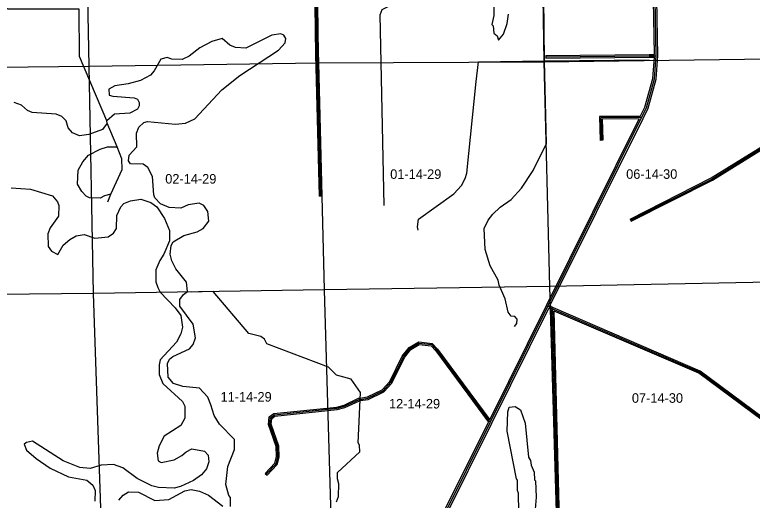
# Model space of a CAD drawing. Extents: x 457167 to 656239, y 1787309 to 1969297.
# Drawn here: x 542162 to 559531, y 1802811 to 1814251 of the extents above; entities that cross this region are included whole.
import ezdxf

# ---------------------------------------------------------------- set-up
doc = ezdxf.new("R2010")
doc.units = 0
for name, color, linetype in [('Level 1', 7, 'Continuous'), ('Level 2', 7, 'Continuous'), ('Level 22', 7, 'Continuous'), ('Level 23', 7, 'Continuous'), ('Level 31', 7, 'Continuous'), ('Level 32', 7, 'Continuous'), ('Level 34', 7, 'Continuous'), ('Level 5', 7, 'Continuous'), ('Level 7', 7, 'Continuous')]:
    doc.layers.add(name, color=color, linetype=linetype)

msp = doc.modelspace()

# ---------------------------------------------------------------- linework, layer by layer
at = {"layer": 'Level 1'}
for p, q in [((543913.495, 1813038.625), (543806.772, 1818560.041)), ((549159.663, 1818551.891), (549316.915, 1813116.23)), ((554522.895, 1818595.745), (554626.091, 1813144.464)), ((554626.091, 1813144.464), (559933.526, 1813210.771)), ((538646.1, 1812984.036), (543913.495, 1813038.625)), ((543913.495, 1813038.625), (549316.915, 1813116.23)), ((544019.338, 1807683.474), (543913.495, 1813038.625)), ((549316.915, 1813116.23), (554626.091, 1813144.464)), ((549316.915, 1813116.23), (549446.786, 1807768.911)), ((554626.091, 1813144.464), (554754.302, 1807847.236)), ((560083.97, 1807951.436), (554754.302, 1807847.236)), ((554754.302, 1807847.236), (549446.786, 1807768.911)), ((554754.302, 1807847.236), (554912.4, 1802537.764)), ((544019.338, 1807683.474), (538702.035, 1807635.269)), ((549446.786, 1807768.911), (544019.338, 1807683.474)), ((544199.322, 1802359.816), (544019.338, 1807683.474)), ((549446.786, 1807768.911), (549606.588, 1802415.358))]:
    msp.add_line(p, q, dxfattribs=at)
at = {"layer": 'Level 22'}
for p, q in [((557268.834, 1813284.999), (557241.795, 1814628.309)), ((554718.957, 1807381.432), (556924.929, 1811827.401)), ((553360.949, 1804642.301), (554718.957, 1807381.432)), ((550520.034, 1798947.821), (553360.949, 1804642.301))]:
    msp.add_line(p, q, dxfattribs=at)
msp.add_lwpolyline([(556924.929, 1811827.401), (557040.277, 1812060.181), (557225.653, 1812743.309), (557268.834, 1813284.999)], dxfattribs=at)
at = {"layer": 'Level 23'}
for p, q in [((557228.23, 1813314.579), (557202.395, 1814598.118)), ((557308.868, 1813283.809), (557281.788, 1814629.114)), ((554683.125, 1807399.21), (556865.177, 1811796.969)), ((554767.031, 1807388.324), (556960.761, 1811809.622)), ((553349.241, 1804708.737), (554683.12, 1807399.199)), ((553396.787, 1804624.533), (554740.32, 1807334.464)), ((550502.28, 1799001.834), (553319.245, 1804648.311)), ((550555.828, 1798929.964), (553396.743, 1804624.444))]:
    msp.add_line(p, q, dxfattribs=at)
for points in [[(556895.047, 1811857.186), (557002.698, 1812074.435), (557186.075, 1812750.196), (557226.28, 1813254.555)], [(556960.77, 1811809.641), (557077.855, 1812045.928), (557265.231, 1812736.422), (557308.868, 1813283.809)]]:
    msp.add_lwpolyline(points, dxfattribs=at)
at = {"layer": 'Level 31'}
for p, q in [((554667.655, 1813258.509), (557101.201, 1813283.261)), ((557101.201, 1813283.261), (557268.834, 1813284.999)), ((554835.432, 1807314.209), (554718.957, 1807381.432))]:
    msp.add_line(p, q, dxfattribs=at)
for points in [[(549365.557, 1809979.888), (549282.662, 1813314.591), (549262.15, 1815056.791), (549179.714, 1818541.679)], [(556924.929, 1811827.401), (555965.95, 1811820.502), (555978.873, 1811291.39)], [(556666.727, 1809410.332), (558578.061, 1810380.549), (560056.031, 1811293.429)], [(560237.928, 1804424.068), (560021.472, 1804541.346), (558291.11, 1805829.426), (554835.432, 1807314.209)], [(555060.472, 1797876.787), (555028.798, 1798543.761), (554956.38, 1802654.014), (554835.432, 1807314.209)], [(550295.708, 1805187.916), (550478.118, 1805216.854), (550837.206, 1805390.746), (551021.051, 1805590.589), (551314.388, 1806189.75), (551473.364, 1806389.664), (551682.17, 1806514.168), (551982.013, 1806479.879), (552098.642, 1806354.467), (553360.949, 1804642.301)], [(548081, 1803422.288), (548315.058, 1803671.788), (548356.978, 1803838.572), (548349.387, 1804080.406), (548167.271, 1804597.645), (548184.623, 1804756.136), (548276.298, 1804822.415), (549752.27, 1804977.097), (549927.406, 1805026.416), (550269.879, 1805183.988), (550295.708, 1805187.916)]]:
    msp.add_lwpolyline(points, dxfattribs=at)
at = {"layer": 'Level 32'}
for p, q in [((554667.35, 1813288.507), (557100.897, 1813313.259)), ((554667.35, 1813288.507), (554667.96, 1813228.509)), ((554667.96, 1813228.509), (557101.506, 1813253.261)), ((557100.891, 1813313.259), (557228.23, 1813314.579)), ((557101.512, 1813253.261), (557226.28, 1813254.555)), ((556008.865, 1811292.123), (555948.882, 1811290.657)), ((549335.566, 1809979.143), (549395.549, 1809980.633)), ((556653.148, 1809437.083), (556680.307, 1809383.581)), ((554805.879, 1807296.626), (554740.32, 1807334.464)), ((554848.9, 1807341.075), (554767.032, 1807388.324)), ((548059.12, 1803442.814), (548102.88, 1803401.762))]:
    msp.add_line(p, q, dxfattribs=at)
for points in [[(549395.549, 1809980.633), (549312.659, 1813315.141), (549292.147, 1815057.323), (549209.705, 1818542.389)], [(549335.566, 1809979.143), (549252.666, 1813314.042), (549232.155, 1815056.261), (549149.722, 1818540.969)], [(556895.047, 1811857.187), (555935.213, 1811850.282), (555948.882, 1811290.657)], [(556865.176, 1811796.969), (555996.686, 1811790.722), (556008.865, 1811292.123)], [(556653.148, 1809437.083), (558563.363, 1810406.732), (560037.328, 1811317.137)], [(556680.307, 1809383.581), (558592.76, 1810354.366), (560027.587, 1811240.598)], [(555030.505, 1797875.364), (554998.81, 1798542.785), (554926.386, 1802653.361), (554805.88, 1807296.626)], [(560206.863, 1804475.021), (560037.658, 1804566.698), (558306.194, 1805855.597), (554848.9, 1807341.075)], [(560211.777, 1804404.115), (560005.286, 1804515.995), (558276.025, 1805803.254), (554866.639, 1807268.148)], [(555090.438, 1797878.21), (555058.785, 1798544.737), (554986.375, 1802654.668), (554866.639, 1807268.147)], [(550291.199, 1805217.575), (550469.036, 1805245.788), (550818.992, 1805415.259), (550996.023, 1805607.694), (551288.877, 1806205.87), (551453.294, 1806412.625), (551675.51, 1806545.126), (551996.434, 1806508.426), (552121.775, 1806373.646), (553349.241, 1804708.737)], [(550300.409, 1805158.286), (550487.2, 1805187.919), (550855.42, 1805366.234), (551046.08, 1805573.484), (551339.898, 1806173.63), (551493.435, 1806366.703), (551688.83, 1806483.211), (551967.592, 1806451.331), (552075.51, 1806335.289), (553319.245, 1804648.311)], [(548059.12, 1803442.814), (548287.859, 1803686.642), (548326.861, 1803841.82), (548319.547, 1804074.822), (548136.705, 1804594.121), (548156.251, 1804772.643), (548265.209, 1804851.418), (549746.599, 1805006.667), (549917.007, 1805054.656), (550261.185, 1805213.012), (550291.199, 1805217.575)], [(548102.88, 1803401.762), (548342.258, 1803656.934), (548387.095, 1803835.324), (548379.228, 1804085.988), (548197.836, 1804601.167), (548212.995, 1804739.628), (548287.388, 1804793.412), (549757.94, 1804947.526), (549937.806, 1804998.178), (550278.572, 1805154.965), (550300.218, 1805158.256)]]:
    msp.add_lwpolyline(points, dxfattribs=at)
at = {"layer": 'Level 5'}
for p, q in [((554640.334, 1813164.453), (554620.229, 1814706.756)), ((554640.334, 1813164.453), (557099.632, 1813189.983)), ((544340.238, 1811696.744), (544332.097, 1811755.095)), ((544571.887, 1811137.458), (544340.238, 1811696.744)), ((544351.016, 1809846.016), (544426.605, 1810020.85))]:
    msp.add_line(p, q, dxfattribs=at)
for points in [[(550861.428, 1809758.605), (550767.393, 1814252.191), (550817.803, 1814377.064), (551118.396, 1814526.17), (551177.046, 1814626.012), (551168.975, 1814709.403), (551085.903, 1814793.034), (550994.341, 1814843.343), (550994.5, 1814885.024), (551220.86, 1815284.453), (551479.972, 1815508.709), (552540.932, 1816213.893), (553093.684, 1817012.441), (553546.234, 1817761.269), (553596.514, 1817844.471)], [(544332.097, 1811755.095), (543686.672, 1813266.06), (543681.901, 1814383.116), (542006.275, 1814380.146), (541914.714, 1814422.116), (541781.75, 1814555.896), (541481.815, 1814606.893), (541415.254, 1814640.432), (541457.363, 1814782.015), (541571.029, 1816440.581), (541572.405, 1816865.728)], [(551659.855, 1809172.516), (551643.445, 1809255.906), (551669.003, 1809430.9), (552504.56, 1810028.469), (552680.251, 1810227.984), (552772.471, 1810394.418), (552806.24, 1810519.33), (553029.854, 1812677.736), (553081.35, 1813144.413), (554640.334, 1813164.453)], [(553928.462, 1806906.119), (553987.012, 1806972.651), (553995.701, 1807080.983), (553937.52, 1807139.503), (553854.189, 1807148.132), (553779.456, 1807240.062), (553713.773, 1807557.036), (553573.107, 1807882.61), (553548.455, 1807999.411), (553357.8, 1808333.454), (553242.305, 1808717.288), (553218.9, 1809217.556), (553311.189, 1809409), (553420.02, 1809550.353), (553595.6, 1809716.528), (553854.623, 1809899.104), (554097.224, 1810165.081), (554373.665, 1810581.051), (554684.133, 1811213.624), (554640.334, 1813164.453)], [(544426.605, 1810020.85), (544695.224, 1810603.541), (544687.681, 1810853.666), (544571.887, 1811137.458)], [(549738.757, 1802776.326), (549789.196, 1802901.208), (549798.484, 1803201.282), (549765.502, 1803318.084), (549765.99, 1803468.136), (550292.714, 1803949.98), (550284.873, 1804108.392), (550251.721, 1804166.852), (550305.501, 1805350.441), (550081.435, 1805667.933), (549739.949, 1805760.711), (549548.794, 1805944.731), (548100.046, 1806499.541), (548042.024, 1806608.102), (547958.862, 1806666.722), (547675.657, 1806742.63), (546836.825, 1807728.995), (546328.287, 1807713.958)]]:
    msp.add_lwpolyline(points, dxfattribs=at)
at = {"layer": 'Level 7'}
for points in [[(553445.668, 1814977.246), (553443.305, 1814235.314), (553400.936, 1814018.701), (553425.847, 1813993.631), (553441.969, 1813818.508), (553525.131, 1813751.548), (553558.153, 1813651.416), (553675.323, 1813792.741), (553759.462, 1814042.565), (553793.53, 1814267.549)], [(544887.385, 1810736.306), (544837.594, 1810811.496), (544854.693, 1810944.809), (545038.714, 1811135.954), (545031.43, 1811461.099), (545081.87, 1811602.651), (545198.941, 1811710.665), (545290.702, 1811735.386), (545949.103, 1811674.933), (546182.586, 1811699.196), (546399.659, 1811798.541), (547035.372, 1812480.089), (547461.635, 1812820.539), (548372.194, 1813417.84), (548531.135, 1813592.414), (548548.144, 1813692.386), (548498.353, 1813767.576), (548431.761, 1813801.116), (548214.918, 1813768.453), (547605.381, 1813461.971), (547363.698, 1813479.398), (547230.515, 1813538.177), (547047.57, 1813688.817), (546805.628, 1813622.913), (546521.705, 1813473.747), (546270.993, 1813274.491), (546104, 1813199.988), (545862.247, 1813200.776), (545754.005, 1813242.775), (545603.823, 1813201.592), (545444.583, 1812926.976), (545360.893, 1812827.203), (545127.09, 1812702.919), (544835.056, 1812620.504), (544518.142, 1812579.8), (544376.13, 1812496.896), (544384.042, 1812355.145), (544475.644, 1812329.875), (544975.722, 1812294.931), (545050.654, 1812261.321), (545092.075, 1812186.161), (545091.805, 1812102.799), (545049.895, 1812027.907), (544874.514, 1811928.454), (544507.649, 1811904.589), (544332.097, 1811755.095)], [(544340.238, 1811696.744), (544231.408, 1811547.011), (543905.894, 1811431.355), (543689.06, 1811398.691), (543522.557, 1811465.911), (543422.885, 1811582.941), (543373.392, 1811749.833), (543273.68, 1811850.193), (543140.497, 1811908.972), (542573.728, 1811944.116), (542465.515, 1811994.466), (542324.192, 1812119.966), (542149.359, 1812187.215)], [(544426.605, 1810020.85), (544276.454, 1809987.967), (544176.222, 1809929.936), (543926.159, 1809939.092), (543842.897, 1809972.701), (543743.254, 1810089.702), (543643.741, 1810256.754), (543653.128, 1810590.169), (543762.118, 1810781.583), (543896.028, 1810939.547), (544171.551, 1811080.382), (544346.803, 1811138.176), (544571.887, 1811137.458)], [(547245.85, 1802667.523), (547246.538, 1802875.936), (547204.986, 1802926.116), (547130.813, 1803184.77), (547182.17, 1803609.756), (547333.498, 1804009.405), (547334.246, 1804242.828), (546985.267, 1804602.399), (546860.883, 1804811.201), (546778.3, 1805061.583), (546712.167, 1805236.836), (546512.822, 1805454.236), (546121.115, 1805488.822), (545904.601, 1805564.531), (545771.708, 1805715.011), (545756.045, 1806031.826), (545806.365, 1806131.728), (545881.615, 1806198.16), (546274.009, 1806380.317), (546366.04, 1806480.06), (546416.549, 1806638.283), (546367.575, 1806963.557), (546052.106, 1807381.39), (546052.625, 1807539.782), (546136.355, 1807656.225), (546228.275, 1807730.957), (546203.993, 1807947.771), (545954.886, 1808265.332), (545863.773, 1808449.024), (545822.61, 1808607.546), (545848.279, 1808815.879), (545890.219, 1808899.111), (546140.801, 1809048.386), (546457.875, 1809139.071), (546599.817, 1809213.634), (546733.757, 1809388.278), (546709.465, 1809613.421), (546618.232, 1809755.432), (546501.68, 1809814.182), (546243.126, 1809773.318), (546076.144, 1809690.475), (545801.11, 1809708.031), (545592.965, 1809792.051), (545460.042, 1809934.191), (545435.261, 1810009.312), (545403.286, 1810442.898), (545295.603, 1810651.63), (545187.46, 1810727.02), (544887.385, 1810736.306)], [(542076.228, 1810170.053), (542534.655, 1810143.578), (543050.985, 1809983.552), (543167.228, 1809841.441), (543200.319, 1809757.981), (543191.191, 1809507.926), (542998.581, 1809233.451), (542939.761, 1809091.897), (542947.155, 1808791.793), (543030.187, 1808683.162), (543179.95, 1808599.303), (543305.71, 1808823.988), (543456.19, 1808956.881), (543606.502, 1809039.755), (543798.365, 1809072.507), (544048.16, 1808988.33), (544365.074, 1809020.694), (544490.375, 1809103.636), (544557.395, 1809211.809), (544566.712, 1809520.214), (544659.102, 1809728.328), (544734.352, 1809803.131), (544884.604, 1809869.333), (545134.828, 1809901.886), (545367.982, 1809826.108), (545509.405, 1809725.618), (545691.92, 1809449.926), (545807.705, 1809166.134), (545806.957, 1808924.39), (545672.558, 1808608.034), (545580.369, 1808458.271), (545487.989, 1808241.826), (545487.072, 1807958.391), (545528.324, 1807824.88), (545586.355, 1807716.309), (545943.635, 1807348.368), (546076.429, 1807164.546), (546108.891, 1806889.353), (546075.053, 1806731.061), (545974.393, 1806539.656), (545589.581, 1806115.745), (545564.212, 1805999.103), (545563.494, 1805774.02), (545646.167, 1805565.357), (546111.659, 1805138.726), (546169.66, 1805030.166), (546168.773, 1804746.731), (546076.514, 1804571.957), (545683.89, 1804323.119), (545566.47, 1804090.054), (545515.891, 1803923.501), (545540.313, 1803740.028), (545606.875, 1803698.118), (545915.539, 1803763.833), (546099.27, 1803863.277), (546199.561, 1803954.68), (546333.173, 1804020.952), (546633.118, 1803969.956), (546716.15, 1803869.655), (546732.372, 1803719.562)], [(554038.12, 1802087.387), (554024.3, 1802979.401), (553999.49, 1803037.821), (554000.267, 1803287.906), (553975.356, 1803313.016), (553762.183, 1804439.1), (553771.989, 1804897.567), (553805.698, 1805005.839), (553947.45, 1805022.051), (554072.233, 1804938.301), (554179.617, 1804629.498), (554260.426, 1803828.946), (554310.188, 1803745.426), (554326.499, 1803637.025), (554392.661, 1803470.063), (554400.444, 1803294.971), (554425.354, 1803269.901), (554440.818, 1802886.365), (554371.415, 1802036.291)], [(546732.372, 1803719.562), (546681.793, 1803553.01), (546556.322, 1803411.676), (546372.5, 1803278.891), (546063.597, 1803138.156), (545913.415, 1803096.933), (545546.65, 1803114.779), (545388.397, 1803148.647), (545047.16, 1803324.786), (544706.162, 1803575.956), (544489.678, 1803651.664), (544197.844, 1803635.941), (543939.19, 1803561.736), (543697.466, 1803579.163), (543306.189, 1803738.821), (542582.404, 1804199.609), (542440.581, 1804175.057), (542382.101, 1804133.576), (542439.994, 1803991.654), (542664.459, 1803790.864), (542997.186, 1803564.745), (543430.025, 1803363.266), (543863.282, 1803286.861), (544004.605, 1803169.701), (544054.227, 1803044.53), (544045.07, 1802786.096)], [(544612.008, 1802809.313), (544712.469, 1802934.026), (544837.74, 1803008.659), (545079.464, 1802999.571), (545462.311, 1802806.593), (545787.516, 1802830.587), (546171.61, 1803029.426), (546313.462, 1803062.307), (546513.395, 1803028.34), (546721.48, 1802927.651), (547062.447, 1802668.121)]]:
    msp.add_lwpolyline(points, dxfattribs=at)

# ---------------------------------------------------------------- texts
at = {"layer": 'Level 2'}
for s, p in [('01-14-29', (551004.097, 1810382.916)), ('06-14-30', (556561.923, 1810384.901)), ('02-14-29', (545706.282, 1810272.191)), ('11-14-29', (547008.364, 1805135.431)), ('12-14-29', (550975.484, 1804972.881)), ('07-14-30', (556696.261, 1805107.659))]:
    msp.add_text(s, height=225, dxfattribs=at).set_placement(p)
at = {"layer": 'Level 34'}
for height, rotation, p in [(25, 271.1526083, (557240.593, 1814066.931)), (25, 74.8170944, (557116.075, 1812291.779)), (25, 63.6100556, (555784.004, 1809499.83)), (24.99916, 63.6280999, (554002.047, 1805907.272))]:
    msp.add_text('STATE HWY 11', height=height, rotation=rotation, dxfattribs=at).set_placement(p)

doc.saveas('drawing.dxf')
